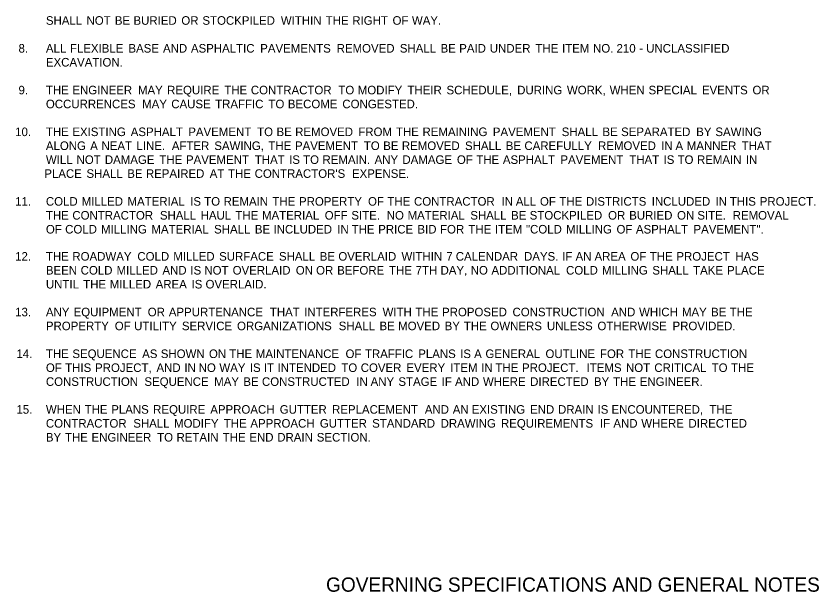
# Model space of a CAD drawing. Extents: x 1930579 to 1935504, y 596431 to 597414.
# Drawn here: x 1934799 to 1935475, y 596431 to 596915 of the extents above; entities that cross this region are included whole.
import ezdxf

# ---------------------------------------------------------------- set-up
doc = ezdxf.new("R2010")
doc.units = 0
doc.layers.add('Default', color=7, linetype='Continuous')
doc.layers.add('R_Border', color=7, linetype='Continuous')

msp = doc.modelspace()

# ---------------------------------------------------------------- texts
at = {"layer": 'Default'}
for s, p in [('SHALL', (1934824.2, 596907.36)), (' NOT', (1934855.72, 596907.36)), (' BE', (1934879.55, 596907.36)), (' BURIED', (1934895.23, 596907.36)), (' OR', (1934935.5, 596907.36)), (' STOCKPILED', (1934953.24, 596907.36)), (' WITHIN', (1935019.24, 596907.36)), (' THE', (1935056.96, 596907.36)), (' RIGHT', (1935079.34, 596907.36)), (' OF', (1935113.23, 596907.36)), (' WAY.', (1935129.53, 596907.36)), ('8.', (1934801.15, 596883.96)), ('ALL', (1934824.2, 596883.96)), (' FLEXIBLE', (1934841.74, 596883.96)), (' BASE', (1934890.97, 596883.96)), (' AND', (1934920.07, 596883.96)), (' ASPHALTIC', (1934943.57, 596883.96)), (' PAVEMENTS', (1935001.87, 596883.96)), (' REMOVED', (1935066.2, 596883.96)), (' SHALL', (1935119.33, 596883.96)), (' BE', (1935153.64, 596883.96)), (' PAID', (1935169.32, 596883.96)), (' UNDER', (1935195.05, 596883.96)), (' THE', (1935233.48, 596883.96)), (' ITEM', (1935255.86, 596883.96)), (' NO.', (1935281.93, 596883.96)), (' 210', (1935301.73, 596883.96)), (' -', (1935320.82, 596883.96)), (' UNCLASSIFIED', (1935326.65, 596883.96)), ('EXCAVATION.', (1934824.2, 596872.26)), ('9.', (1934801.15, 596848.86)), ('THE', (1934824.2, 596848.86)), (' ENGINEER', (1934843.79, 596848.86)), (' MAY', (1934899, 596848.86)), (' REQUIRE', (1934923.52, 596848.86)), (' THE', (1934971.61, 596848.86)), (' CONTRACTOR', (1934993.99, 596848.86)), (' TO', (1935067.63, 596848.86)), (' MODIFY', (1935083.95, 596848.86)), (' THEIR', (1935125.79, 596848.86)), (' SCHEDULE,', (1935158.63, 596848.86)), (' DURING', (1935218.11, 596848.86)), (' WORK,', (1935259.95, 596848.86)), (' WHEN', (1935295.94, 596848.86)), (' SPECIAL', (1935328.65, 596848.86)), (' EVENTS', (1935373.58, 596848.86)), (' OR', (1935416.11, 596848.86)), ('OCCURRENCES', (1934824.2, 596837.16)), (' MAY', (1934902.5, 596837.16)), (' CAUSE', (1934927.02, 596837.16)), (' TRAFFIC', (1934963.94, 596837.16)), (' TO', (1935008.81, 596837.16)), (' BECOME', (1935025.12, 596837.16)), (' CONGESTED.', (1935070.99, 596837.16)), ('10.', (1934798.35, 596813.76)), ('THE', (1934824.2, 596813.76)), (' EXISTING', (1934843.79, 596813.76)), (' ASPHALT', (1934892.91, 596813.76)), (' PAVEMENT', (1934941.35, 596813.76)), (' TO', (1934999.29, 596813.76)), (' BE', (1935015.61, 596813.76)), (' REMOVED', (1935031.29, 596813.76)), (' FROM', (1935084.41, 596813.76)), (' THE', (1935116.07, 596813.76)), (' REMAINING', (1935138.45, 596813.76)), (' PAVEMENT', (1935197.62, 596813.76)), (' SHALL', (1935255.56, 596813.76)), (' BE', (1935289.87, 596813.76)), (' SEPARATED', (1935305.55, 596813.76)), (' BY', (1935368.75, 596813.76)), (' SAWING', (1935384.89, 596813.76)), ('ALONG', (1934824.2, 596802.06)), (' A', (1934858.79, 596802.06)), (' NEAT', (1934868.32, 596802.06)), (' LINE.', (1934897.74, 596802.06)), ('  AFTER', (1934924.81, 596802.06)), (' SAWING,', (1934963.24, 596802.06)), (' THE', (1935008.74, 596802.06)), (' PAVEMENT', (1935031.12, 596802.06)), (' TO', (1935089.06, 596802.06)), (' BE', (1935105.37, 596802.06)), (' REMOVED', (1935121.05, 596802.06)), (' SHALL', (1935174.18, 596802.06)), (' BE', (1935208.49, 596802.06)), (' CAREFULLY', (1935224.17, 596802.06)), (' REMOVED', (1935286.15, 596802.06)), (' IN', (1935339.27, 596802.06)), (' A', (1935351.3, 596802.06)), (' MANNER', (1935360.82, 596802.06)), (' THAT', (1935407.08, 596802.06)), ('WILL', (1934824.2, 596790.36)), (' NOT', (1934847.32, 596790.36)), (' DAMAGE', (1934871.15, 596790.36)), (' THE', (1934917.01, 596790.36)), (' PAVEMENT', (1934939.39, 596790.36)), (' THAT', (1934997.33, 596790.36)), (' IS', (1935026.19, 596790.36)), (' TO', (1935037.96, 596790.36)), (' REMAIN.', (1935054.27, 596790.36)), (' ANY', (1935098.11, 596790.36)), (' DAMAGE', (1935121.52, 596790.36)), (' OF', (1935167.38, 596790.36)), (' THE', (1935183.68, 596790.36)), (' ASPHALT', (1935206.06, 596790.36)), (' PAVEMENT', (1935254.5, 596790.36)), (' THAT', (1935312.44, 596790.36)), (' IS', (1935341.3, 596790.36)), (' TO', (1935353.07, 596790.36)), (' REMAIN', (1935369.39, 596790.36)), (' IN', (1935410.49, 596790.36)), ('   PLACE', (1934814.84, 596778.66)), (' SHALL', (1934855.68, 596778.66)), (' BE', (1934889.99, 596778.66)), (' REPAIRED', (1934905.67, 596778.66)), (' AT', (1934959.36, 596778.66)), (' THE', (1934974.81, 596778.66)), (" CONTRACTOR'S", (1934997.19, 596778.66)), (' EXPENSE.', (1935079.07, 596778.66)), ('11.', (1934798.35, 596755.26)), ('COLD', (1934824.2, 596755.26)), (' MILLED', (1934851.62, 596755.26)), (' MATERIAL', (1934890.21, 596755.26)), (' IS', (1934942.95, 596755.26)), (' TO', (1934954.73, 596755.26)), (' REMAIN', (1934971.04, 596755.26)), (' THE', (1935012.14, 596755.26)), (' PROPERTY', (1935034.52, 596755.26)), (' OF', (1935092.59, 596755.26)), (' THE', (1935108.89, 596755.26)), (' CONTRACTOR', (1935131.27, 596755.26)), (' IN', (1935204.91, 596755.26)), (' ALL', (1935216.94, 596755.26)), (' OF', (1935237.27, 596755.26)), (' THE', (1935253.58, 596755.26)), (' DISTRICTS', (1935275.95, 596755.26)), (' INCLUDED', (1935331.32, 596755.26)), (' IN', (1935385, 596755.26)), (' THIS', (1935397.03, 596755.26)), (' PROJECT.', (1935422.22, 596755.26)), ('THE', (1934824.2, 596743.56)), (' CONTRACTOR', (1934843.79, 596743.56)), (' SHALL', (1934917.43, 596743.56)), (' HAUL', (1934951.74, 596743.56)), (' THE', (1934981.01, 596743.56)), (' MATERIAL', (1935003.39, 596743.56)), (' OFF', (1935056.14, 596743.56)), (' SITE.', (1935078.59, 596743.56)), ('  NO', (1935105.66, 596743.56)), (' MATERIAL', (1935125.89, 596743.56)), (' SHALL', (1935178.64, 596743.56)), (' BE', (1935212.95, 596743.56)), (' STOCKPILED', (1935228.63, 596743.56)), (' OR', (1935294.62, 596743.56)), (' BURIED', (1935312.37, 596743.56)), (' ON', (1935352.64, 596743.56)), (' SITE.', (1935369.7, 596743.56)), ('  REMOVAL', (1935396.77, 596743.56)), ('OF', (1934824.2, 596731.86)), (' COLD', (1934837.72, 596731.86)), (' MILLING', (1934867.92, 596731.86)), (' MATERIAL', (1934910.32, 596731.86)), (' SHALL', (1934963.07, 596731.86)), (' BE', (1934997.38, 596731.86)), (' INCLUDED', (1935013.06, 596731.86)), (' IN', (1935066.74, 596731.86)), (' THE', (1935078.77, 596731.86)), (' PRICE', (1935101.15, 596731.86)), (' BID', (1935134.16, 596731.86)), (' FOR', (1935153.18, 596731.86)), (' THE', (1935177.08, 596731.86)), (' ITEM', (1935199.45, 596731.86)), (' "COLD', (1935225.52, 596731.86)), (' MILLING', (1935259.3, 596731.86)), (' OF', (1935301.7, 596731.86)), (' ASPHALT', (1935318.01, 596731.86)), (' PAVEMENT".', (1935366.45, 596731.86)), ('12.', (1934798.35, 596709.05)), ('THE', (1934824.2, 596709.05)), (' ROADWAY', (1934843.79, 596709.05)), (' COLD', (1934898.49, 596709.05)), (' MILLED', (1934928.7, 596709.05)), (' SURFACE', (1934967.29, 596709.05)), (' SHALL', (1935017.62, 596709.05)), (' BE', (1935051.93, 596709.05)), (' OVERLAID', (1935067.61, 596709.05)), (' WITHIN', (1935120.74, 596709.05)), (' 7', (1935158.47, 596709.05)), (' CALENDAR', (1935166.4, 596709.05)), (' DAYS.', (1935223.85, 596709.05)), (' IF', (1935255.96, 596709.05)), (' AN', (1935267.23, 596709.05)), (' AREA', (1935283.18, 596709.05)), (' OF', (1935313.39, 596709.05)), (' THE', (1935329.69, 596709.05)), (' PROJECT', (1935352.07, 596709.05)), (' HAS', (1935401.62, 596709.05)), ('BEEN', (1934824.2, 596697.35)), (' COLD', (1934850.78, 596697.35)), (' MILLED', (1934880.99, 596697.35)), (' AND', (1934919.58, 596697.35)), (' IS', (1934943.08, 596697.35)), (' NOT', (1934954.85, 596697.35)), (' OVERLAID', (1934978.67, 596697.35)), (' ON', (1935031.81, 596697.35)), (' OR', (1935048.87, 596697.35)), (' BEFORE', (1935066.62, 596697.35)), (' THE', (1935110.25, 596697.35)), (' 7TH', (1935132.62, 596697.35)), (' DAY,', (1935153.61, 596697.35)), (' NO', (1935178.99, 596697.35)), (' ADDITIONAL', (1935196.43, 596697.35)), (' COLD', (1935259.23, 596697.35)), (' MILLING', (1935289.44, 596697.35)), (' SHALL', (1935331.84, 596697.35)), (' TAKE', (1935366.15, 596697.35)), (' PLACE', (1935394.69, 596697.35)), ('UNTIL', (1934824.2, 596685.65)), (' THE', (1934852.91, 596685.65)), (' MILLED', (1934875.29, 596685.65)), (' AREA', (1934913.88, 596685.65)), (' IS', (1934944.09, 596685.65)), (' OVERLAID.', (1934955.86, 596685.65)), ('13.', (1934798.35, 596662.25)), ('ANY', (1934824.2, 596662.25)), (' EQUIPMENT', (1934844.82, 596662.25)), (' OR', (1934907.22, 596662.25)), (' APPURTENANCE', (1934924.97, 596662.25)), (' THAT', (1935009.97, 596662.25)), (' INTERFERES', (1935038.83, 596662.25)), (' WITH', (1935104.82, 596662.25)), (' THE', (1935132.5, 596662.25)), (' PROPOSED', (1935154.88, 596662.25)), (' CONSTRUCTION', (1935214.17, 596662.25)), (' AND', (1935297.18, 596662.25)), (' WHICH', (1935320.68, 596662.25)), (' MAY', (1935356.75, 596662.25)), (' BE', (1935381.27, 596662.25)), (' THE', (1935396.94, 596662.25)), ('PROPERTY', (1934824.2, 596650.55)), (' OF', (1934879.48, 596650.55)), (' UTILITY', (1934895.78, 596650.55)), (' SERVICE', (1934935.95, 596650.55)), (' ORGANIZATIONS', (1934982.37, 596650.55)), (' SHALL', (1935067.93, 596650.55)), (' BE', (1935102.24, 596650.55)), (' MOVED', (1935117.92, 596650.55)), (' BY', (1935157.07, 596650.55)), (' THE', (1935173.21, 596650.55)), (' OWNERS', (1935195.59, 596650.55)), (' UNLESS', (1935243.13, 596650.55)), (' OTHERWISE', (1935285.65, 596650.55)), (' PROVIDED.', (1935348.83, 596650.55)), ('14.', (1934799.4, 596627.15)), ('THE', (1934824.2, 596627.15)), (' SEQUENCE', (1934843.79, 596627.15)), (' AS', (1934902.52, 596627.15)), (' SHOWN', (1934918.2, 596627.15)), (' ON', (1934958.74, 596627.15)), (' THE', (1934975.8, 596627.15)), (' MAINTENANCE', (1934998.18, 596627.15)), (' OF', (1935073.66, 596627.15)), (' TRAFFIC', (1935089.97, 596627.15)), (' PLANS', (1935134.84, 596627.15)), (' IS', (1935170.1, 596627.15)), (' A', (1935181.87, 596627.15)), (' GENERAL', (1935191.39, 596627.15)), (' OUTLINE', (1935241.91, 596627.15)), (' FOR', (1935287.76, 596627.15)), (' THE', (1935311.66, 596627.15)), (' CONSTRUCTION', (1935334.04, 596627.15)), ('OF', (1934824.2, 596615.45)), (' THIS', (1934837.72, 596615.45)), (' PROJECT,', (1934862.9, 596615.45)), (' AND', (1934914.55, 596615.45)), (' IN', (1934938.05, 596615.45)), (' NO', (1934950.08, 596615.45)), (' WAY', (1934967.51, 596615.45)), (' IS', (1934993.15, 596615.45)), (' IT', (1935004.92, 596615.45)), (' INTENDED', (1935016.45, 596615.45)), (' TO', (1935070.13, 596615.45)), (' COVER', (1935086.44, 596615.45)), (' EVERY', (1935124.88, 596615.45)), (' ITEM', (1935161.71, 596615.45)), (' IN', (1935187.78, 596615.45)), (' THE', (1935199.81, 596615.45)), (' PROJECT.', (1935222.19, 596615.45)), ('  ITEMS', (1935273.85, 596615.45)), (' NOT', (1935309.66, 596615.45)), (' CRITICAL', (1935333.48, 596615.45)), (' TO', (1935381.75, 596615.45)), (' THE', (1935398.07, 596615.45)), ('CONSTRUCTION', (1934824.2, 596603.75)), (' SEQUENCE', (1934904.42, 596603.75)), (' MAY', (1934963.15, 596603.75)), (' BE', (1934987.67, 596603.75)), (' CONSTRUCTED', (1935003.35, 596603.75)), (' IN', (1935082.74, 596603.75)), (' ANY', (1935094.77, 596603.75)), (' STAGE', (1935118.17, 596603.75)), (' IF', (1935154.54, 596603.75)), (' AND', (1935165.81, 596603.75)), (' WHERE', (1935189.31, 596603.75)), (' DIRECTED', (1935229.01, 596603.75)), (' BY', (1935282.69, 596603.75)), (' THE', (1935298.83, 596603.75)), (' ENGINEER.', (1935321.21, 596603.75)), ('15.', (1934799.4, 596580.35)), ('WHEN', (1934824.2, 596580.35)), (' THE', (1934854.12, 596580.35)), (' PLANS', (1934876.5, 596580.35)), (' REQUIRE', (1934911.76, 596580.35)), (' APPROACH', (1934959.85, 596580.35)), (' GUTTER', (1935018.3, 596580.35)), (' REPLACEMENT', (1935062.32, 596580.35)), (' AND', (1935140.38, 596580.35)), (' AN', (1935163.88, 596580.35)), (' EXISTING', (1935179.83, 596580.35)), (' END', (1935228.95, 596580.35)), (' DRAIN', (1935252.45, 596580.35)), (' IS', (1935285.72, 596580.35)), (' ENCOUNTERED,', (1935297.49, 596580.35)), (' THE', (1935379.89, 596580.35)), ('CONTRACTOR', (1934824.2, 596568.65)), (' SHALL', (1934895.05, 596568.65)), (' MODIFY', (1934929.36, 596568.65)), (' THE', (1934971.2, 596568.65)), (' APPROACH', (1934993.58, 596568.65)), (' GUTTER', (1935052.03, 596568.65)), (' STANDARD', (1935096.05, 596568.65)), (' DRAWING', (1935153.65, 596568.65)), (' REQUIREMENTS', (1935204.43, 596568.65)), (' IF', (1935287.75, 596568.65)), (' AND', (1935299.03, 596568.65)), (' WHERE', (1935322.52, 596568.65)), (' DIRECTED', (1935362.23, 596568.65)), ('BY', (1934824.2, 596556.95)), (' THE', (1934837.55, 596556.95)), (' ENGINEER', (1934859.93, 596556.95)), (' TO', (1934915.14, 596556.95)), (' RETAIN', (1934931.45, 596556.95)), (' THE', (1934970.32, 596556.95)), (' END', (1934992.7, 596556.95)), (' DRAIN', (1935016.2, 596556.95)), (' SECTION.', (1935049.47, 596556.95))]:
    msp.add_text(s, height=7.2, rotation=360, dxfattribs=at).set_placement(p)
at = {"layer": 'R_Border'}
msp.add_text('GOVERNING SPECIFICATIONS AND GENERAL NOTES ', height=12, rotation=360, dxfattribs=at).set_placement((1935059.94, 596430.69))

doc.saveas('drawing.dxf')
